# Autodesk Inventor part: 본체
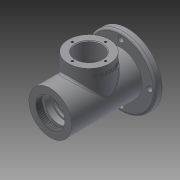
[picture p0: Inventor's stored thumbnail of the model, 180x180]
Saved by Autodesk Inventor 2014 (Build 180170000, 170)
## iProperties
Created: 2016-08
Part Number: 본체
Material: 일반
Document SubType Name: Modeling
Designer: USER
Density: 1 g/cm^3
Appearance: 기본값
Author: USER
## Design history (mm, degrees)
sketch "스케치1"
  geometry: L1 (-57.5, 0)-(57.5, 0); L2 (-57.5, 0)-(-57.5, 31); L3 (-57.5, 31)-(57.5, 31); L4 (57.5, 31)-(57.5, 0); 2 further points
  constraints: 8 end point, 3 perpendicular, 1 coincident, 1 horizontal, 1 horizontal alignment, 1 midpoint
  dimensions: "d0" = 115 distance between parallel lines of L4 L2; "d1" = 62 diameter of L3 L1
revolve "회전1" sketch "스케치1" stored, may be unused: angle "d2" = 90 deg
node "작업 평면1"
sketch "스케치2"
  geometry: C1 r 50 at (0, 0); 1 further point
  constraints: 1 centre point, 1 coincident
  dimensions: "d4" = 100 diameter of C1
extrude "돌출1" join sketch "스케치2" distance "d5" = 10; taper "d6" = 0 deg
sketch "스케치4"
  geometry: L1 (-57.5, -31)-(-57.5, 31) reference; L2 (57.5, -31)-(57.5, 31) reference; L3 (-57.5, 0)-(57.5, 0); L4 (-57.5, 0)-(-57.5, 21); L5 (-57.5, 21)-(-48.5, 21); L6 (-48.5, 21)-(-48.5, 24); L7 (-48.5, 24)-(-45.5, 24); L8 (-45.5, 24)-(-45.5, 20); L9 (-45.5, 20)-(-36.5, 20); L10 (-36.5, 20)-(-36.5, 17.5); L11 (-36.5, 17.5)-(-33.25, 17.5); L12 (-33.25, 17.5)-(-33.25, 18.5); L13 (-33.25, 18.5)-(-31.5, 18.5); L14 (-31.5, 18.5)-(-31.5, 17.5); L15 (-31.5, 17.5)-(-20.5, 17.5); L16 (57.5, 21)-(43.5, 16); L17 (43.5, 16)-(43.5, 12.5); L18 (43.5, 12.5)-(36.2, 12.5); L19 (36.2, 12.5)-(36.2, 10); L20 (36.2, 10)-(33.5, 10); L21 (33.5, 10)-(33.5, 16.5); L22 (33.5, 16.5)-(28.5, 16.5); L23 (28.5, 16.5)-(28.5, 17.5); L24 (28.5, 17.5)-(17.5, 17.5); L25 (17.5, 17.5)-(17.5, 26); L26 (17.5, 26)-(-20.5, 26); L27 (-20.5, 26)-(-20.5, 17.5); 1 further point
  constraints: 50 end point, 13 parallel, 9 perpendicular, 2 midpoint, 2 point on line, 1 collinear, 1 horizontal alignment
  dimensions: "d35" = 3 distance between parallel lines of L8 L6; "d37" = 21 distance between parallel lines of L10 L1; "d38" = 26 distance between parallel lines of L14 L1; "d39" = 1.75 distance between parallel lines of L14 L12; "d40" = 37 diameter of L13 L3; "d41" = 35 diameter of L11 L3; "d42" = 40 diameter of L9 L3; "d43" = 48 diameter of L7 L3; "d44" = 42 diameter of L5 L3; "d45" = 14 distance between parallel lines of L2 L17; "d46" = 7.3 distance between parallel lines of L19 L17; "d47" = 2.7 distance between parallel lines of L19 L21; "d49" = 38 distance between parallel lines of L25 L27; "d50" = 60 distance between parallel lines of L14 L23; "d52" = 52 diameter of L26 L3; "d53" = 35 diameter of L24 L3; "d54" = 33 diameter of L22 L3; "d55" = 20 diameter of L20 L3; "d56" = 25 diameter of L18 L3; "d57" = 32 diameter of L16.end L3; "d58" = 42 diameter of L16.start L3; "d127" = 12 distance between parallel lines of L8 L4
revolve "회전2" sketch "스케치4" stored, may be unused: angle "d59" = 90 deg
node "작업 평면2"
sketch "스케치5"
  geometry: L1 (31, -57.5)-(-31, -57.5) reference; C1 r 30 at (0, -1.5); 2 further points
  constraints: 1 centre point, 1 midpoint, 1 vertical alignment
  dimensions: "d67" = 60 diameter of C1; "d68" = 56 distance from line of C1.centre L1
extrude "돌출2" join sketch "스케치5" stored distance "d62" = 13; taper "d63" = 0 deg
sketch "스케치9"
  geometry: C1 r 50 at (0, 0) reference; C2 r 31 at (0, 0) reference; C3 r 4 at (0, 41.5); C4 r 4 at (-41.5, 0); C5 r 4 at (0, -41.5); C6 r 4 at (41.5, 0); A1 r 41.5 centre (0, 0) between (0, 41.5) and (-41.5, 0)
  constraints: 5 centre point, 4 point on circle, 2 horizontal alignment, 2 vertical alignment, 1 coincident
  dimensions: "d72" = 83 diameter of A1; "d73" = 8 diameter of C3; "d74" = 8 diameter of C4; "d75" = 8 diameter of C5; "d76" = 8 diameter of C6
extrude "돌출3" cut sketch "스케치9" stored distance "d77" = 13; taper "d78" = 0 deg
node "작업 평면3"
sketch "스케치10"
  geometry: L1 (-30, 0)-(30, 0) reference; L2 (-56, -80)-(-56, -18) reference; 2 further points
  constraints: 1 other
  dimensions: "d79" = 10 distance from line of point (0, -10) L1; "d80" = 56 distance from line of L2 point (0, -10)
feature "엠보싱1" sketch "스케치10" dims "d0" = 115, "d1" = 62, "d35" = 3, "d37" = 21, "d38" = 26, "d39" = 1.75, "d40" = 37, "d41" = 35, "d42" = 40, "d43" = 48, "d44" = 42, "d45" = 14, "d46" = 7.3, "d47" = 2.7, "d49" = 38, "d50" = 60, "d52" = 52, "d53" = 35, "d54" = 33, "d55" = 20, "d56" = 25, "d57" = 32, "d58" = 42, "d81" = 0.5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
feature "스레드1" dims "d83" = 10, "d84" = 0
fillet "모깎기1" dims "d96" = 3
chamfer "모따기2" distance "d97" = 0.7; stored, may be unused: second distance "d98" = 2, angle "d99" = 30 deg
fillet "모깎기2" dims "d100" = 0.3
fillet "모깎기3" dims "d101" = 3
chamfer "모따기3" distance "d102" = 1; stored, may be unused: second distance "d103" = 2, angle "d104" = 30 deg
chamfer "모따기4" distance "d105" = 1; stored, may be unused: second distance "d106" = 2, angle "d107" = 30 deg
fillet "모깎기4" dims "d108" = 0.3
sketch "스케치18"
  geometry: C1 r 30 at (0, 0) reference; C2 r 19 at (0, 0); 1 further point
  constraints: 1 centre point, 1 coincident
  dimensions: "d110" = 38 diameter of C2
extrude "돌출4" cut sketch "스케치18" distance "d111" = 45; taper "d112" = 0 deg
chamfer "모따기5" distance "d113" = 1; stored, may be unused: second distance "d114" = 2, angle "d115" = 30 deg
fillet "모깎기6" dims "d116" = 3
fillet "모깎기7" dims "d117" = 3
sketch "스케치22"
  geometry: C1 r 30 at (0, 0) reference; C2 r 20 at (0, 0) reference; A1 r 24 centre (0, 0) between (0, 24) and (-24, 0); 3 further points
  constraints: 4 point on circle, 2 horizontal alignment, 2 vertical alignment, 1 centre point, 1 coincident
  dimensions: "d118" = 48 diameter of A1
hole "구멍2" sketch "스케치22" at (0, 24), (-24, 0), (0, -24), (24, 0) diameter "d119" = 3.242; stored, may be unused: countersink angle "d123" = 90 deg, drill point angle "d125" = 118 deg; dims "d120" = 8, "d121" = 4, "d122" = 2, "d124" = 10
fillet "모깎기8" dims "d126" = 3
node "솔리드1"
other parameters: "d3" = -3, "d60" = 49
